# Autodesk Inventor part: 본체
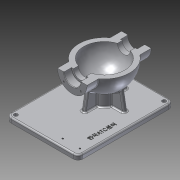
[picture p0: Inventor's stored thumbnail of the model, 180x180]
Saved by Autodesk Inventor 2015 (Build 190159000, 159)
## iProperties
Created: 2015-12
Part Number: 본체
Material: 알루미늄 6061
Document SubType Name: Modeling
Designer: mduedu
Density: 2.71 g/cm^3
Appearance: 알루미늄 - 평지
Mass: 1388.35 g
Surface Area: 1121.73 cm^2
Volume: 512.305 cm^3
Author: mduedu
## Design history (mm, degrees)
sketch "스케치1"
  geometry: L1 (-53, 0)-(53, 0); A1 r 53 centre (0, 0) between (53, 0) and (-53, 0); 2 further points
  constraints: 2 coincident, 2 end point, 2 point on circle, 1 centre point, 1 horizontal, 1 midpoint
  dimensions: "d0" = 53 radius of A1
revolve "회전1" sketch "스케치1" stored, may be unused: angle "d2" = 90 deg
feature "쉘1" dims "d11" = 10
node "작업 평면1"
sketch "스케치2"
  geometry: C1 r 31 at (0, 0); 1 further point
  constraints: 1 centre point, 1 coincident
  dimensions: "d4" = 62 diameter of C1
extrude "돌출1" join sketch "스케치2" stored distance "d5" = 10; taper "d6" = 0 deg
hole "구멍1" diameter "d14" = 35; stored, may be unused: countersink angle "d18" = 90 deg, drill point angle "d20" = 0 deg; dims "d12" = 10, "d13" = 10, "d15" = 6, "d16" = 4, "d17" = 2, "d19" = 16
hole "구멍2" diameter "d23" = 27; stored, may be unused: countersink angle "d27" = 90 deg, drill point angle "d29" = 0 deg; dims "d21" = 10, "d22" = 10, "d24" = 6, "d25" = 4, "d26" = 2, "d28" = 16
fillet "모깎기1" dims "d30" = 0.3
chamfer "모따기1" distance "d40" = 1; stored, may be unused: second distance "d41" = 2, angle "d42" = 45 deg
sketch "스케치4"
  geometry: L1 (0, 0)-(0, -25); L2 (0, 0)-(-17.678, -17.678); A1 r 25 centre (0, 0) between (-17.678, -17.678) and (0, -25); 1 further point
  constraints: 4 end point, 2 point on circle, 1 centre point, 1 coincident, 1 vertical
  dimensions: "d43" = 50 diameter of A1; "d47" = 45 deg angle of L1 L2
hole "구멍4" sketch "스케치4" at (-17.678, -17.678) diameter "d49" = 3.242; stored, may be unused: countersink angle "d53" = 90 deg, drill point angle "d55" = 118 deg; dims "d50" = 11, "d51" = 4, "d52" = 2, "d54" = 13
node "작업 평면3"
sketch "스케치6" dims "d22" = 10
  geometry: L1 (-70, -75)-(130, -75); L2 (130, -75)-(130, 75); L3 (130, 75)-(-70, 75); L4 (-70, 75)-(-70, -75); 2 further points
  constraints: 8 end point, 2 parallel, 1 coincident, 1 horizontal, 1 perpendicular
  dimensions: "d158" = 200 distance of L3.end L2.end; "d159" = 150 distance of L2.end L1.end; "d162" = 75 distance from line of L1 point (0, 0); "d163" = 70 distance from line of L4 point (0, 0)
extrude "돌출3" join sketch "스케치6" distance "d80" = 10; taper "d81" = 0 deg
sketch "스케치7"
  geometry: C1 r 20 at (0, 0); 2 further points
  constraints: 2 coincident, 1 centre point
  dimensions: "d82" = 40 diameter of C1
extrude "돌출4" join sketch "스케치7" stored distance "d84" = 10; taper "d85" = 0 deg
sketch "스케치8"
  geometry: 3 further points
  constraints: 2 coincident
hole "구멍6" sketch "스케치8" at (0, 0) diameter "d86" = 20; stored, may be unused: countersink angle "d90" = 90 deg, drill point angle "d92" = 118 deg; dims "d87" = 7, "d88" = 40, "d89" = 5, "d91" = 10
fillet "모깎기2" dims "d93" = 0.3
sketch "스케치9"
  geometry: L1 (-45, -75)-(-38.245, -36.692); L2 (70, -75)-(-130, -75) reference; A1 r 53 centre (0, 0) between (42.988, 31) and (42.988, -31) reference; 1 further point
  constraints: 2 end point, 1 coincident, 1 point on circle, 1 point on line
  dimensions: "d94" = 45 horizontal distance of L1.start point (0, 0); "d160" = 80 deg angle of L2 L1
feature "리브1" sketch "스케치9" dims "d96" = 1, "d97" = 8, "d98" = 0, "d99" = 0, "d100" = 1, "d101" = 1
fillet "모깎기3" dims "d120" = 3
fillet "모깎기4" dims "d121" = 3, "d122" = 3
fillet "모깎기5" dims "d123" = 3
sketch "스케치12"
  geometry: L1 (0, 100)-(0, -100); L2 (0, 100)-(100, 100); L3 (100, 100)-(100, -100); L4 (100, -100)-(0, -100); 2 further points
  constraints: 8 end point, 3 perpendicular, 1 coincident, 1 midpoint, 1 vertical
  dimensions: "d127" = 200 distance of L2.end L3.end; "d129" = 100 distance between parallel lines of L1 L3
extrude "돌출5" cut sketch "스케치12" stored distance "d130" = 10; taper "d131" = 0 deg
fillet "모깎기10" dims "d164" = 10
fillet "모깎기11" dims "d165" = 3
sketch "스케치15"
  geometry: C1 r 4 at (-120, 65); C2 r 4 at (60, 65); C3 r 4 at (60, -65); A1 r 10 centre (-120, 65) between (-120, 75) and (-130, 65) reference; A2 r 10 centre (60, 65) between (70, 65) and (60, 75) reference; A3 r 10 centre (60, -65) between (60, -75) and (70, -65) reference; 1 further point
  constraints: 3 centre point, 3 coincident, 2 equal radius
  dimensions: "d166" = 8 diameter of C1
extrude "돌출8" cut sketch "스케치15" stored distance "d167" = 10; taper "d168" = 0 deg
sketch "스케치16"
  geometry: L1 (-130, 65)-(-130, -65) reference; L2 (-120, -75)-(60, -75) reference; 2 further points
  constraints: 1 other
  dimensions: "d169" = 70 distance from line of point (-60, -55) L1; "d170" = 20 distance from line of point (-60, -55) L2
feature "엠보싱2" sketch "스케치16" dims "d171" = 0.5, "d172" = 0
sketch "스케치17"
  geometry: L1 (-120, 75)-(60, 75) reference; L2 (-130, -65)-(-130, 65) reference; 2 further points
  constraints: 1 vertical alignment
  dimensions: "d180" = 12 distance from line of L1 point (-114, 63); "d181" = 16 distance from line of point (-114, 63) L2; "d182" = 36 distance of point (-114, 27) point (-114, 63)
hole "구멍9" sketch "스케치17" at (-114, 63), (-114, 27) diameter "d173" = 3.242; stored, may be unused: countersink angle "d177" = 90 deg, drill point angle "d179" = 0 deg; dims "d174" = 6, "d175" = 4, "d176" = 2, "d178" = 8
node "솔리드1"
mirror "대칭1"
mirror "대칭2"
pattern_circular "원형 패턴1" dims angle "d57" = 360 deg
mirror "대칭3"
pattern_circular "원형 패턴3" dims angle "d103" = 360 deg
other parameters: "d3" = 67, "d77" = -85
